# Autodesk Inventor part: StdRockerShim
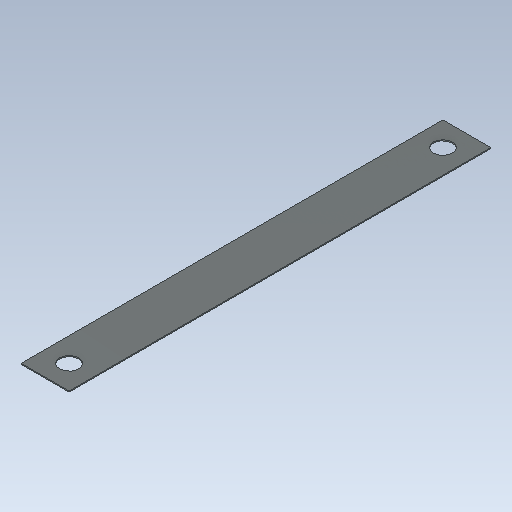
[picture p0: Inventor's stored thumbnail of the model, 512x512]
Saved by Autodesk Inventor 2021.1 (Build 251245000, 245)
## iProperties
Created: 2019-05
Part Number: StdRockerShim
Material: Steel, Galvanized
Document SubType Name: Modeling
Designer: u1426
Density: 7.85 g/cm^3
Appearance: Galvanized
BoltDiameter: 2.000 in
MasonryEdgeDist: 2.500 in
MasonryLength: 44.000 in
MasonryWidth: 5.000 in
d71: 2.000 in
Author: u1426
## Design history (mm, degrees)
sketch "MasonryPL"
  geometry: L1 (63.5, 0)-(63.5, 2.54); L2 (63.5, 0)-(-63.5, 0); L3 (-63.5, 0)-(-63.5, 2.54); L4 (-63.5, 2.54)-(63.5, 2.54); A1 r 609.6 centre (0, -603.744) between (63.5, 2.54) and (-63.5, 2.54); 1 further point
  constraints: 8 end point, 2 point on circle, 2 vertical, 1 centre point, 1 horizontal, 1 horizontal alignment, 1 midpoint, 1 perpendicular, 1 other
  dimensions: "d84" = 609.6 radius of A1; "d89" = 2.54 distance between parallel lines of L4 L2 (= ShimThickness)
extrude "MasonryPlate" new body sketch "MasonryPL" taper "d70" = 0 deg
sketch "MasonryPLHole"
  geometry: L1 (127, -1117.6)-(127, 0) reference; L2 (0, -1117.6)-(0, 0) reference; L3 (127, 0)-(0, 0) reference; L4 (127, -1117.6)-(0, -1117.6) reference; 3 further points
  dimensions: "d79" = 63.5 distance from line of point (63.5, -63.5) L1 (derived); "d80" = 63.5 distance from line of point (63.5, -1054.1) L2 (= d79); "d90" = 63.5 distance from line of point (63.5, -63.5) L3 (derived); "d91" = 63.5 distance from line of point (63.5, -1054.1) L4 (derived)
hole "MasonryHoles" sketch "MasonryPLHole" at (63.5, -63.5), (63.5, -1054.1) stored, may be unused: countersink angle "d75" = 82 deg, drill point angle "d77" = 118 deg; dims "d72" = 19.05, "d73" = 9.525, "d74" = 6.35, "d76" = 25.4
body "Solid4"
other parameters: "ShimThickness" = 2.54 [user parameter; used in 1 equation term]
